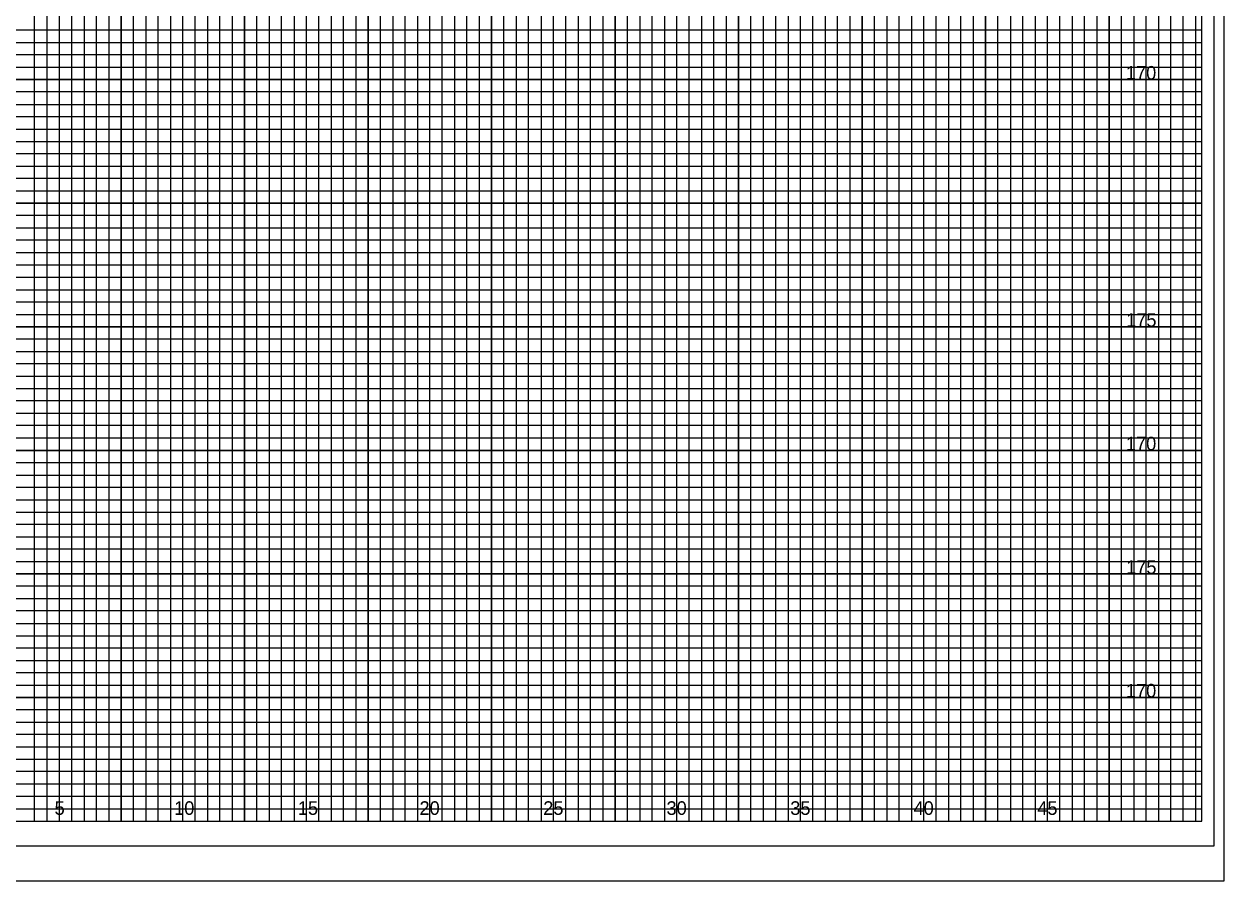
# Model space of a CAD drawing. Extents: x -4 to 103, y -2 to 67.
# Drawn here: x 54.82 to 103.4, y -2.43 to 32.25 of the extents above; entities that cross this region are included whole.
import ezdxf

# ---------------------------------------------------------------- set-up
doc = ezdxf.new("R2010")
doc.units = 0
for name, color, linetype in [('Exist XS Ground Line', 7, 'Continuous'), ('Old_Level_10', 7, 'Continuous'), ('Old_Level_16', 7, 'Continuous'), ('Old_Level_3', 7, 'Continuous'), ('Old_Level_5', 7, 'Continuous'), ('Old_Level_8', 7, 'Continuous'), ('Prop XS Dump Level', 7, 'Continuous'), ('Prop XS Finish Grade', 7, 'Continuous'), ('Prop XS Suitable Common Exc Shape', 7, 'Continuous')]:
    doc.layers.add(name, color=color, linetype=linetype)

msp = doc.modelspace()

# ---------------------------------------------------------------- linework, layer by layer
at = {"layer": 'Exist XS Ground Line'}
msp.add_lwpolyline([(103, 66), (-2.8, 66), (-2.8, -1), (103, -1)], close=True, dxfattribs=at)
at = {"layer": 'Old_Level_10'}
for p, q in [((56.25, 0), (56.25, 65)), ((58.75, 0), (58.75, 65)), ((61.25, 0), (61.25, 65)), ((63.75, 0), (63.75, 65)), ((66.25, 0), (66.25, 65)), ((68.75, 0), (68.75, 65)), ((71.25, 0), (71.25, 65)), ((73.75, 0), (73.75, 65)), ((91.25, 0), (91.25, 63.425)), ((93.75, 0), (93.75, 63.425)), ((96.25, 0), (96.25, 63.425)), ((98.75, 0), (98.75, 63.425)), ((101.25, 0), (101.25, 63.425)), ((76.25, 0), (76.25, 62)), ((78.75, 0), (78.75, 62)), ((81.25, 0), (81.25, 62)), ((83.75, 0), (83.75, 62)), ((86.25, 0), (86.25, 62)), ((88.75, 0), (88.75, 62)), ((0, 30), (102.5, 30)), ((0, 27.5), (102.5, 27.5)), ((0, 25), (102.5, 25)), ((0, 22.5), (102.5, 22.5)), ((0, 20), (102.5, 20)), ((0, 17.5), (102.5, 17.5)), ((0, 15), (102.5, 15)), ((0, 12.5), (102.5, 12.5)), ((0, 10), (102.5, 10)), ((0, 7.5), (102.5, 7.5)), ((0, 5), (102.5, 5)), ((0, 2.5), (102.5, 2.5))]:
    msp.add_line(p, q, dxfattribs=at)
at = {"layer": 'Old_Level_3'}
msp.add_line((-3.5, -2.425), (102.1625, -2.425), dxfattribs=at)
at = {"layer": 'Old_Level_5'}
msp.add_lwpolyline([(103.4, 67.4), (-3.5, 67.4), (-3.5, -2.425), (103.4, -2.425)], close=True, dxfattribs=at)
at = {"layer": 'Old_Level_8'}
for points in [[(56.25, 0), (56.25, 65)], [(58.75, 65), (58.75, 0), (61.25, 0), (61.25, 65)], [(63.75, 65), (63.75, 0), (66.25, 0), (66.25, 65)], [(68.75, 65), (68.75, 0), (71.25, 0), (71.25, 65)], [(73.75, 65), (73.75, 0), (76.25, 0), (76.25, 62)], [(88.75, 62), (88.75, 0), (91.25, 0), (91.25, 63.425)], [(93.75, 63.425), (93.75, 0), (96.25, 0), (96.25, 63.425)], [(98.75, 63.425), (98.75, 0), (101.25, 0), (101.25, 63.425)], [(78.75, 62), (78.75, 0), (81.25, 0), (81.25, 62)], [(83.75, 62), (83.75, 0), (86.25, 0), (86.25, 62)], [(0, 27.5), (102.5, 27.5), (102.5, 30), (0, 30)], [(0, 22.5), (102.5, 22.5), (102.5, 25), (0, 25)], [(0, 17.5), (102.5, 17.5), (102.5, 20), (0, 20)], [(0, 12.5), (102.5, 12.5), (102.5, 15), (0, 15)], [(0, 7.5), (102.5, 7.5), (102.5, 10), (0, 10)], [(0, 2.5), (102.5, 2.5), (102.5, 5), (0, 5)]]:
    msp.add_lwpolyline(points, dxfattribs=at)
at = {"layer": 'Prop XS Dump Level'}
msp.add_line((-3.5, -2.425), (103.4, -2.425), dxfattribs=at)
msp.add_lwpolyline([(102.5, 65), (0, 65), (0, 0), (102.5, 0)], close=True, dxfattribs=at)
at = {"layer": 'Prop XS Finish Grade'}
for points in [[(54.75, 0), (55.25, 0), (55.25, 65)], [(55.75, 65), (55.75, 0), (56.75, 0), (56.75, 65)], [(57.25, 65), (57.25, 0), (57.75, 0), (57.75, 65)], [(58.25, 65), (58.25, 0), (59.25, 0), (59.25, 65)], [(59.75, 65), (59.75, 0), (60.25, 0), (60.25, 65)], [(60.75, 65), (60.75, 0), (61.75, 0), (61.75, 65)], [(62.25, 65), (62.25, 0), (62.75, 0), (62.75, 65)], [(63.25, 65), (63.25, 0), (64.25, 0), (64.25, 65)], [(64.75, 65), (64.75, 0), (65.25, 0), (65.25, 65)], [(65.75, 65), (65.75, 0), (66.75, 0), (66.75, 65)], [(67.25, 65), (67.25, 0), (67.75, 0), (67.75, 65)], [(68.25, 65), (68.25, 0), (69.25, 0), (69.25, 65)], [(69.75, 65), (69.75, 0), (70.25, 0), (70.25, 65)], [(70.75, 65), (70.75, 0), (71.75, 0), (71.75, 65)], [(72.25, 65), (72.25, 0), (72.75, 0), (72.75, 65)], [(73.25, 65), (73.25, 0), (74.25, 0), (74.25, 62)], [(89.75, 62), (89.75, 0), (90.25, 0), (90.25, 63.425)], [(90.75, 63.425), (90.75, 0), (91.75, 0), (91.75, 63.425)], [(92.25, 63.425), (92.25, 0), (92.75, 0), (92.75, 63.425)], [(93.25, 63.425), (93.25, 0), (94.25, 0), (94.25, 63.425)], [(94.75, 63.425), (94.75, 0), (95.25, 0), (95.25, 63.425)], [(95.75, 63.425), (95.75, 0), (96.75, 0), (96.75, 63.425)], [(97.25, 63.425), (97.25, 0), (97.75, 0), (97.75, 63.425)], [(98.25, 63.425), (98.25, 0), (99.25, 0), (99.25, 63.425)], [(99.75, 63.425), (99.75, 0), (100.25, 0), (100.25, 63.425)], [(100.25, 63.425), (100.75, 63.425), (100.75, 0), (101.75, 0), (101.75, 63.425), (102.25, 63.425), (102.25, 0)], [(74.75, 62), (74.75, 0), (75.25, 0), (75.25, 62)], [(75.75, 62), (75.75, 0), (76.75, 0), (76.75, 62)], [(77.25, 62), (77.25, 0), (77.75, 0), (77.75, 62)], [(78.25, 62), (78.25, 0), (79.25, 0), (79.25, 62)], [(79.75, 62), (79.75, 0), (80.25, 0), (80.25, 62)], [(80.75, 62), (80.75, 0), (81.75, 0), (81.75, 62)], [(82.25, 62), (82.25, 0), (82.75, 0), (82.75, 62)], [(83.25, 62), (83.25, 0), (84.25, 0), (84.25, 62)], [(84.75, 62), (84.75, 0), (85.25, 0), (85.25, 62)], [(85.75, 62), (85.75, 0), (86.75, 0), (86.75, 62)], [(87.25, 62), (87.25, 0), (87.75, 0), (87.75, 62)], [(88.25, 62), (88.25, 0), (89.25, 0), (89.25, 62)], [(0, 31.5), (102.5, 31.5), (102.5, 32), (0, 32)], [(0, 30.5), (102.5, 30.5), (102.5, 31), (0, 31)], [(0, 29), (102.5, 29), (102.5, 29.5), (0, 29.5)], [(0, 28), (102.5, 28), (102.5, 28.5), (0, 28.5)], [(0, 26.5), (102.5, 26.5), (102.5, 27), (0, 27)], [(0, 25.5), (102.5, 25.5), (102.5, 26), (0, 26)], [(0, 24), (102.5, 24), (102.5, 24.5), (0, 24.5)], [(0, 23), (102.5, 23), (102.5, 23.5), (0, 23.5)], [(0, 21.5), (102.5, 21.5), (102.5, 22), (0, 22)], [(0, 20.5), (102.5, 20.5), (102.5, 21), (0, 21)], [(0, 19), (102.5, 19), (102.5, 19.5), (0, 19.5)], [(0, 18), (102.5, 18), (102.5, 18.5), (0, 18.5)], [(0, 16.5), (102.5, 16.5), (102.5, 17), (0, 17)], [(0, 15.5), (102.5, 15.5), (102.5, 16), (0, 16)], [(0, 14), (102.5, 14), (102.5, 14.5), (0, 14.5)], [(0, 13), (102.5, 13), (102.5, 13.5), (0, 13.5)], [(0, 11.5), (102.5, 11.5), (102.5, 12), (0, 12)], [(0, 10.5), (102.5, 10.5), (102.5, 11), (0, 11)], [(0, 9), (102.5, 9), (102.5, 9.5), (0, 9.5)], [(0, 8), (102.5, 8), (102.5, 8.5), (0, 8.5)], [(0, 6.5), (102.5, 6.5), (102.5, 7), (0, 7)], [(0, 5.5), (102.5, 5.5), (102.5, 6), (0, 6)], [(0, 4), (102.5, 4), (102.5, 4.5), (0, 4.5)], [(0, 3), (102.5, 3), (102.5, 3.5), (0, 3.5)], [(0, 1.5), (102.5, 1.5), (102.5, 2), (0, 2)], [(0, 0.5), (102.5, 0.5), (102.5, 1), (0, 1)]]:
    msp.add_lwpolyline(points, dxfattribs=at)

# ---------------------------------------------------------------- texts
at = {"layer": 'Old_Level_16'}
for s, p in [('5', (56.0574, 0.25)), ('10', (60.8971, 0.25)), ('15', (65.9057, 0.25)), ('20', (70.8312, 0.25)), ('25', (75.8399, 0.25)), ('30', (80.8312, 0.25)), ('35', (85.8399, 0.25)), ('40', (90.8313, 0.25)), ('45', (95.8399, 0.25))]:
    msp.add_text(s, height=0.55, dxfattribs=at).set_placement(p)
at = {"layer": 'Prop XS Suitable Common Exc Shape'}
for s, p in [('170', (99.4296, 30)), ('175', (99.4383, 20)), ('170', (99.4296, 15)), ('175', (99.4383, 10)), ('170', (99.4296, 5))]:
    msp.add_text(s, height=0.55, dxfattribs=at).set_placement(p)

doc.saveas('drawing.dxf')
